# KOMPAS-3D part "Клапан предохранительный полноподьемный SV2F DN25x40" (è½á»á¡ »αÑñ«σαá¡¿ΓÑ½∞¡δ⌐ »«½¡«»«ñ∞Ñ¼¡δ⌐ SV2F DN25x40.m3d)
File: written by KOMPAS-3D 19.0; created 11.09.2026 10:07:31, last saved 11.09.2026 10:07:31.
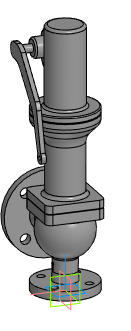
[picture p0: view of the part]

Document properties: Автор: elist; Организация: HP; Полное имя файла: Z:\3.Личные\sachek\Dendor\_3D для проектировщиков\5.9 SV2F. Клапан предохранительный полноподьемный\SV2F_STP\Клапан предохранительный полноподьемный SV2F DN25x40.m3d

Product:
- Part/product: Клапан предохранительный полноподьемный SV2F DN25x40

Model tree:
1. Операция без истории:1  (labels: Клапан предохранительный полноподьемный SV2F DN25x40)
